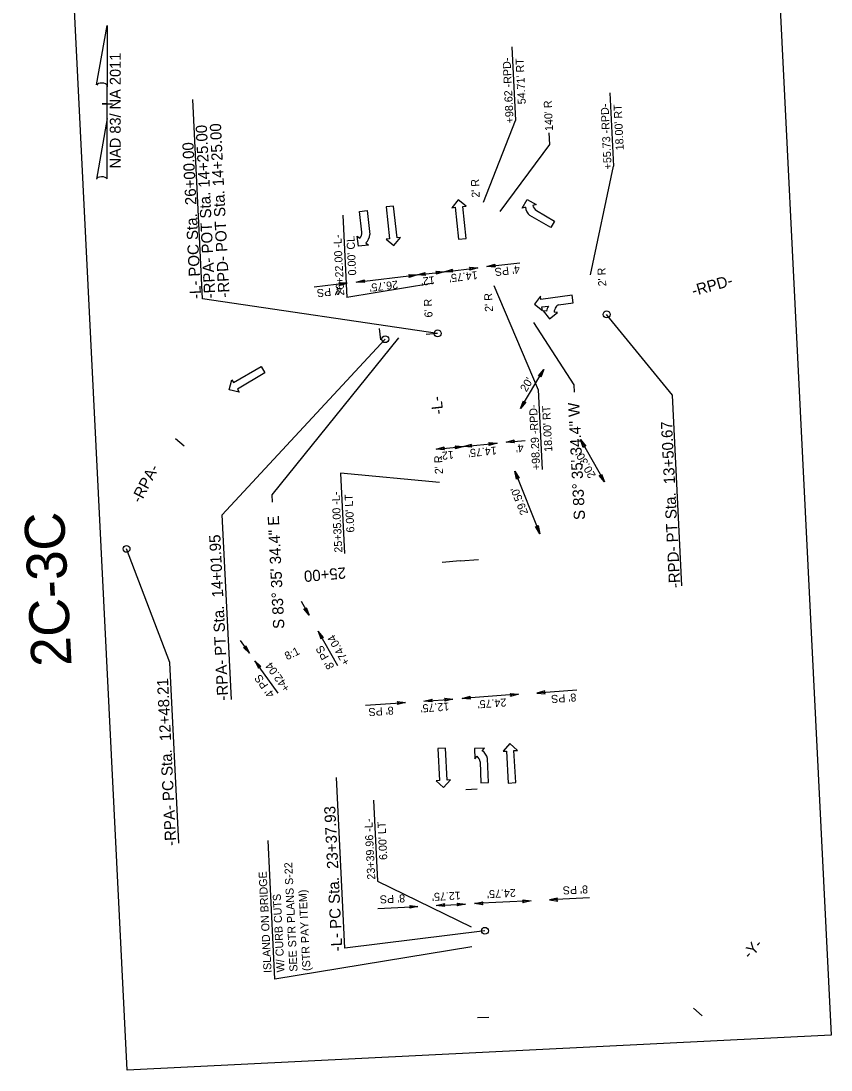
# Model space of a CAD drawing. Extents: x 1807485 to 1808169, y 913841 to 915733.
# Drawn here: x 1807681.6 to 1808035.7, y 914781.9 to 915240.5 of the extents above; entities that cross this region are included whole.
import ezdxf

# ---------------------------------------------------------------- set-up
doc = ezdxf.new("R2010")
doc.units = 0
for name, color, linetype in [('Prop Dimension', 7, 'Continuous'), ('Prop Horizontal Alignment Direction Label', 7, 'Continuous'), ('Prop Horizontal Alignment Station Label', 7, 'Continuous'), ('Prop Horizontal Alignment Tick Label', 7, 'Continuous'), ('Prop Horizontal Alignment Tick Large', 7, 'Continuous'), ('Prop Horizontal Alignment Tick Small', 7, 'Continuous'), ('Prop Lane Arrow CELL', 7, 'Continuous'), ('Prop North Arrow NAD83 for Plan Sheets CELL', 7, 'Continuous'), ('Scratch_Level_3', 7, 'Continuous'), ('Scratch_Level_6', 7, 'Continuous')]:
    doc.layers.add(name, color=color, linetype=linetype)

msp = doc.modelspace()

# ---------------------------------------------------------------- linework, layer by layer
at = {"layer": 'Prop Dimension'}
for p, q in [((1807896.2, 915229.15), (1807897.79, 915197.06)), ((1807939.04, 915209.15), (1807940.63, 915177.06)), ((1807883.84, 915161.26), (1807897.79, 915197.06)), ((1807912.37, 915191.57), (1807912.62, 915186.54)), ((1807912.62, 915186.54), (1807890.86, 915157.25)), ((1807930.56, 915129.57), (1807940.63, 915177.06)), ((1807822.31, 915155.59), (1807824.1, 915119.62)), ((1807861.19, 915125.8), (1807824.1, 915119.62)), ((1807888.27, 915124.82), (1807907.72, 915079.22)), ((1807907.72, 915079.22), (1807909.45, 915044.42)), ((1807864.5, 915038.74), (1807821.27, 915042.81)), ((1807821.27, 915042.81), (1807823.02, 915007.66)), ((1807835.63, 914899.92), (1807837.38, 914864.5)), ((1807792.62, 914821.54), (1807789.61, 914882.28)), ((1807837.38, 914864.5), (1807878.34, 914844.4)), ((1807878.75, 914835.67), (1807792.62, 914821.54))]:
    msp.add_line(p, q, dxfattribs=at)
at = {"layer": 'Prop Horizontal Alignment Direction Label'}
for p, q in [((1807923.42, 915081.37), (1807905.83, 915108.68)), ((1807791.35, 915033.3), (1807846.77, 915102.05)), ((1807923.58, 915078.19), (1807923.42, 915081.37)), ((1807791.5, 915030.13), (1807791.35, 915033.3))]:
    msp.add_line(p, q, dxfattribs=at)
at = {"layer": 'Prop Horizontal Alignment Station Label'}
for p, q in [((1807760.98, 915119.1), (1807756.66, 915206.16)), ((1807863.73, 915103.95), (1807760.98, 915119.1)), ((1807966.37, 915076.91), (1807937.6, 915112.25)), ((1807840.83, 915101.38), (1807769.55, 915024.57)), ((1807970.51, 914993.57), (1807966.37, 915076.91)), ((1807773.56, 914943.92), (1807769.55, 915024.57)), ((1807746.7, 914960.03), (1807727.75, 915009.71)), ((1807750.63, 914881), (1807746.7, 914960.03)), ((1807823.18, 914835.12), (1807819.47, 914909.79)), ((1807884.43, 914842.75), (1807823.18, 914835.12))]:
    msp.add_line(p, q, dxfattribs=at)
for centre in [(1807937.6, 915112.25), (1807863.73, 915103.95), (1807840.83, 915101.38), (1807727.75, 915009.71), (1807884.43, 914842.75)]:
    msp.add_circle(centre, 1.5, dxfattribs=at)
at = {"layer": 'Prop Horizontal Alignment Tick Large'}
for q in [(1807865.68, 915003.75), (1807881.62, 915005.14)]:
    msp.add_line((1807873.65, 915004.45), q, dxfattribs=at)
at = {"layer": 'Prop Horizontal Alignment Tick Small'}
for p, q in [((1807838.89, 915101.15), (1807838.26, 915106.11)), ((1807863.73, 915103.95), (1807858.76, 915103.39)), ((1807752.97, 915054.58), (1807749.15, 915057.82)), ((1807881.07, 914904.73), (1807876.08, 914904.42)), ((1807979.31, 914805.51), (1807975.62, 914808.87)), ((1807886.18, 914804.86), (1807881.19, 914804.63))]:
    msp.add_line(p, q, dxfattribs=at)
at = {"layer": 'Prop Lane Arrow CELL'}
for p, q in [((1807872.77, 915162.36), (1807869.92, 915158.89)), ((1807876.19, 915159.56), (1807872.77, 915162.36)), ((1807900.7, 915158.7), (1807902.88, 915162.53)), ((1807902.88, 915162.53), (1807906.79, 915160.3)), ((1807906.79, 915160.3), (1807905.35, 915159.92)), ((1807829.63, 915157.28), (1807832.91, 915157.64)), ((1807830.62, 915148.18), (1807829.63, 915157.28)), ((1807832.91, 915157.64), (1807834.05, 915147.15)), ((1807844.48, 915159.59), (1807841.2, 915159.23)), ((1807841.2, 915159.23), (1807842.7, 915145.31)), ((1807845.98, 915145.67), (1807844.48, 915159.59)), ((1807869.92, 915158.89), (1807871.41, 915159.05)), ((1807871.41, 915159.05), (1807872.92, 915145.13)), ((1807874.7, 915159.4), (1807876.19, 915159.56)), ((1807876.2, 915145.48), (1807874.7, 915159.4)), ((1807902.13, 915159.08), (1807900.7, 915158.7)), ((1807913.16, 915150.2), (1807904.05, 915155.52)), ((1807906.93, 915157.67), (1807914.82, 915153.05)), ((1807914.82, 915153.05), (1807913.16, 915150.2)), ((1807829.13, 915142.04), (1807828.59, 915146.51)), ((1807828.59, 915146.51), (1807829.75, 915145.58)), ((1807833.5, 915142.56), (1807829.13, 915142.04)), ((1807832.34, 915143.49), (1807833.5, 915142.56)), ((1807842.7, 915145.31), (1807841.21, 915145.15)), ((1807841.21, 915145.15), (1807844.63, 915142.35)), ((1807844.63, 915142.35), (1807847.47, 915145.83)), ((1807847.47, 915145.83), (1807845.98, 915145.67)), ((1807872.92, 915145.13), (1807876.2, 915145.48)), ((1807908.69, 915120.24), (1807906.05, 915116.7)), ((1807908.89, 915118.75), (1807908.69, 915120.24)), ((1807922.56, 915120.63), (1807908.89, 915118.75)), ((1807923.01, 915117.36), (1807922.56, 915120.63)), ((1807906.05, 915116.7), (1807909.55, 915114)), ((1807909.34, 915115.48), (1807912.17, 915115.87)), ((1807909.55, 915114), (1807909.34, 915115.48)), ((1807909.87, 915113.84), (1807912.57, 915110.33)), ((1807911.36, 915113.64), (1807909.87, 915113.84)), ((1807916.62, 915116.48), (1807923.01, 915117.36)), ((1807912.57, 915110.33), (1807916.09, 915113.03)), ((1807916.09, 915113.03), (1807914.65, 915113.23)), ((1807774.51, 915082.39), (1807786.58, 915089.48)), ((1807788.25, 915086.63), (1807776.18, 915079.54)), ((1807786.58, 915089.48), (1807788.25, 915086.63)), ((1807772.66, 915079.32), (1807773.75, 915083.68)), ((1807773.75, 915083.68), (1807774.51, 915082.39)), ((1807776.94, 915078.25), (1807772.66, 915079.32)), ((1807776.18, 915079.54), (1807776.94, 915078.25)), ((1807867.13, 914922.59), (1807863.84, 914922.42)), ((1807863.84, 914922.42), (1807864.58, 914908.44)), ((1807867.88, 914908.61), (1807867.13, 914922.59)), ((1807884.25, 914922.56), (1807879.85, 914922.43)), ((1807879.85, 914922.43), (1807879.99, 914917.93)), ((1807883.24, 914921.47), (1807884.25, 914922.56)), ((1807895.33, 914924.57), (1807892.31, 914921.25)), ((1807892.31, 914921.25), (1807893.8, 914921.33)), ((1807893.8, 914921.33), (1807894.55, 914907.35)), ((1807898.6, 914921.58), (1807895.33, 914924.57)), ((1807897.1, 914921.5), (1807898.6, 914921.58)), ((1807897.84, 914907.52), (1807897.1, 914921.5)), ((1807879.99, 914917.93), (1807880.99, 914919.02)), ((1807882.25, 914916.57), (1807882.63, 914907.43)), ((1807885.92, 914907.57), (1807885.48, 914918.11)), ((1807864.58, 914908.44), (1807863.08, 914908.36)), ((1807863.08, 914908.36), (1807866.35, 914905.38)), ((1807866.35, 914905.38), (1807869.38, 914908.69)), ((1807869.38, 914908.69), (1807867.88, 914908.61)), ((1807882.63, 914907.43), (1807885.92, 914907.57)), ((1807894.55, 914907.35), (1807897.84, 914907.52))]:
    msp.add_line(p, q, dxfattribs=at)
for centre, radius, start, end in [((1807908.56, 915160.48), 3.27, 190.0189, 239.6771), ((1807907.35, 915159.59), 5.25, 185.6893, 231.001), ((1807827.38, 915147.82), 3.27, 316.5434, 6.2016), ((1807828.82, 915147.38), 5.25, 312.2138, 357.5255), ((1807915.8, 915113.35), 4.43, 145.3596, 176.2382), ((1807919.07, 915112.93), 4.43, 145.2658, 176.1194), ((1807917.59, 915114.15), 2.52, 112.4439, 148.7559), ((1807880.35, 914917.1), 5.25, 11.0556, 56.3673), ((1807878.99, 914916.45), 3.27, 2.3796, 52.0377)]:
    msp.add_arc(centre, radius, start, end, dxfattribs=at)
at = {"layer": 'Prop North Arrow NAD83 for Plan Sheets CELL'}
for p, q in [((1807714.68, 915212.54), (1807719.28, 915238.49)), ((1807719.3, 915238.49), (1807719.28, 915238.49)), ((1807719.3, 915238.49), (1807719.28, 915238.49)), ((1807719.3, 915238.49), (1807719.3, 915211.72)), ((1807719.3, 915197.84), (1807719.3, 915212.51)), ((1807719.3, 915211.72), (1807719.3, 915212.48)), ((1807717.06, 915204.33), (1807717.04, 915204.33)), ((1807719.05, 915204.33), (1807717.06, 915204.33)), ((1807717.09, 915204.33), (1807721.57, 915204.33)), ((1807719.3, 915197.84), (1807714.63, 915171.38)), ((1807719.33, 915171.49), (1807719.3, 915197.84))]:
    msp.add_line(p, q, dxfattribs=at)
for centre, start_param, end_param in [((1807717, 915212.26), 0.216388, 2.908219), ((1807717, 915171.28), 0.201328, 3.141593)]:
    msp.add_ellipse(centre, major_axis=(2.37, -0.02), ratio=0.461098, start_param=start_param, end_param=end_param, dxfattribs=at)
at = {"layer": 'Scratch_Level_3'}
msp.add_lwpolyline([(1807728.07, 914781.87), (1807681.6, 915717.81), (1807989.22, 915733.08), (1808035.69, 914797.14)], close=True, dxfattribs=at)
at = {"layer": 'Scratch_Level_6'}
for p, q in [((1807866.65, 915130.91), (1807881.3, 915132.65)), ((1807885.27, 915133.12), (1807899.69, 915134.84)), ((1807828.18, 915126.33), (1807854.74, 915129.49)), ((1807854.74, 915129.49), (1807866.65, 915130.91)), ((1807824.2, 915125.86), (1807809.79, 915124.14)), ((1807899.91, 915071.03), (1807910.16, 915088.21)), ((1807863.07, 915053.29), (1807875.01, 915054.47)), ((1807875.01, 915054.47), (1807889.68, 915055.94)), ((1807893.66, 915056.33), (1807902.01, 915057.16)), ((1807926.17, 915057.52), (1807936.66, 915038.98)), ((1807897.47, 915043.74), (1807908.41, 915016.34)), ((1807807.57, 914980.72), (1807804.2, 914986.67)), ((1807820.13, 914958.56), (1807811.49, 914973.81)), ((1807781.52, 914964.07), (1807777.53, 914969.62)), ((1807794.06, 914946.58), (1807783.85, 914960.82)), ((1807857.71, 914943.15), (1807870.42, 914944.06)), ((1807899.1, 914946.13), (1807874.41, 914944.35)), ((1807924.56, 914947.96), (1807907.08, 914946.7)), ((1807832.25, 914941.32), (1807849.73, 914942.57)), ((1807930.07, 914857.09), (1807912.57, 914856.22)), ((1807837.63, 914852.52), (1807855.14, 914853.39)), ((1807863.13, 914853.78), (1807875.86, 914854.41)), ((1807904.58, 914855.83), (1807879.86, 914854.61))]:
    msp.add_line(p, q, dxfattribs=at)
for points in [[(1807877.65, 915132.84), (1807881.3, 915132.65), (1807877.78, 915131.59), (1807878.16, 915132.28)], [(1807888.92, 915132.93), (1807885.27, 915133.12), (1807888.79, 915134.19), (1807888.41, 915133.5)], [(1807851.09, 915129.68), (1807854.74, 915129.49), (1807851.22, 915128.43), (1807851.6, 915129.12)], [(1807858.39, 915129.3), (1807854.74, 915129.49), (1807858.26, 915130.55), (1807857.88, 915129.86)], [(1807863.01, 915131.1), (1807866.65, 915130.91), (1807863.14, 915129.85), (1807863.52, 915130.54)], [(1807870.3, 915130.72), (1807866.65, 915130.91), (1807870.17, 915131.97), (1807869.79, 915131.28)], [(1807820.7, 915124.82), (1807824.2, 915125.86), (1807820.53, 915126.07), (1807821.07, 915125.48)], [(1807831.82, 915126.14), (1807828.18, 915126.33), (1807831.7, 915127.39), (1807831.31, 915126.7)], [(1807907.78, 915085.43), (1807910.16, 915088.21), (1807908.85, 915084.77), (1807908.54, 915085.49)], [(1807902.29, 915073.8), (1807899.91, 915071.03), (1807901.22, 915074.46), (1807901.53, 915073.74)], [(1807866.71, 915053.03), (1807863.07, 915053.29), (1807866.6, 915054.28), (1807866.21, 915053.6)], [(1807871.36, 915054.74), (1807875.01, 915054.47), (1807871.47, 915053.48), (1807871.86, 915054.16)], [(1807878.65, 915054.21), (1807875.01, 915054.47), (1807878.54, 915055.47), (1807878.15, 915054.79)], [(1807886.04, 915056.2), (1807889.68, 915055.94), (1807886.14, 915054.94), (1807886.54, 915055.62)], [(1807897.31, 915056.07), (1807893.66, 915056.33), (1807897.2, 915057.33), (1807896.81, 915056.65)], [(1807927.4, 915054.08), (1807926.17, 915057.52), (1807928.51, 915054.68), (1807927.73, 915054.77)], [(1807898.23, 915040.17), (1807897.47, 915043.74), (1807899.41, 915040.61), (1807898.64, 915040.8)], [(1807935.43, 915042.42), (1807936.66, 915038.98), (1807934.32, 915041.81), (1807935.11, 915041.73)], [(1807907.65, 915019.92), (1807908.41, 915016.34), (1807906.48, 915019.47), (1807907.24, 915019.28)], [(1807806.33, 914984.16), (1807807.57, 914980.72), (1807805.23, 914983.56), (1807806.01, 914983.47)], [(1807813.8, 914970.98), (1807811.49, 914973.81), (1807812.72, 914970.34), (1807813.05, 914971.06)], [(1807779.92, 914967.35), (1807781.52, 914964.07), (1807778.89, 914966.64), (1807779.68, 914966.63)], [(1807786.45, 914958.25), (1807783.85, 914960.82), (1807785.44, 914957.5), (1807785.69, 914958.25)], [(1807866.79, 914944.42), (1807870.42, 914944.06), (1807866.86, 914943.16), (1807867.27, 914943.84)], [(1807878.05, 914943.99), (1807874.41, 914944.35), (1807877.98, 914945.25), (1807877.56, 914944.58)], [(1807895.46, 914946.49), (1807899.1, 914946.13), (1807895.53, 914945.23), (1807895.95, 914945.9)], [(1807910.62, 914947.58), (1807907.08, 914946.7), (1807910.73, 914946.32), (1807910.23, 914946.93)], [(1807846.09, 914942.93), (1807849.73, 914942.57), (1807846.16, 914941.68), (1807846.57, 914942.35)], [(1807861.34, 914942.79), (1807857.71, 914943.15), (1807861.27, 914944.05), (1807860.86, 914943.37)], [(1807916.13, 914857.02), (1807912.57, 914856.22), (1807916.21, 914855.76), (1807915.72, 914856.38)], [(1807851.51, 914853.83), (1807855.14, 914853.39), (1807851.55, 914852.57), (1807851.98, 914853.23)], [(1807866.75, 914853.34), (1807863.13, 914853.78), (1807866.71, 914854.6), (1807866.28, 914853.94)], [(1807872.23, 914854.85), (1807875.86, 914854.41), (1807872.28, 914853.59), (1807872.7, 914854.25)], [(1807883.48, 914854.16), (1807879.86, 914854.61), (1807883.44, 914855.42), (1807883.01, 914854.76)], [(1807900.95, 914856.27), (1807904.58, 914855.83), (1807900.99, 914855.01), (1807901.42, 914855.67)]]:
    msp.add_lwpolyline(points, close=True, dxfattribs=at)

# ---------------------------------------------------------------- texts
at = {"layer": 'Prop Dimension'}
for s, p in [('+98.62 -RPD-', (1807896.99, 915195.86)), ("54.71' RT", (1807902.27, 915204.19)), ("140' R", (1807914.21, 915192.5)), ('+55.73 -RPD-', (1807939.83, 915175.73)), ("18.00' RT", (1807945.11, 915184.05)), ("2' R", (1807882.16, 915163.35)), ('26+22.00 -L-', (1807822.93, 915120.56)), ("0.00' CL", (1807828.18, 915129.35)), ("2' R", (1807937.46, 915124.6)), ("6' R", (1807861.55, 915110.97)), ("2' R", (1807887.93, 915113.48)), ('+98.29 -RPD-', (1807908.59, 915044.24)), ("18.00' RT", (1807913.89, 915052.26)), ("2' R", (1807866.08, 915042.5)), ('25+35.00 -L-', (1807822.13, 915008.16)), ("6.00' LT", (1807827.38, 915016.95)), ('23+39.96 -L-', (1807836.49, 914865.2)), ("6.00' LT", (1807841.75, 914873.8)), ('SEE STR PLANS S-22', (1807802.51, 914824.95)), ('ISLAND ON BRIDGE', (1807791.15, 914824.39)), ('W/ CURB CUTS', (1807796.83, 914824.67)), ('(STR PAY ITEM)', (1807808.19, 914825.24))]:
    msp.add_text(s, height=3.5, rotation=92.8422, dxfattribs=at).set_placement(p)
at = {"layer": 'Prop Horizontal Alignment Direction Label'}
for s, rotation, p in [('-RPD-', 15.5231, (1807975.54, 915120.12)), ('-L-', 96.3677, (1807866.28, 915068.72)), ('S 83%%d 35\' 34.4" W', 92.8422, (1807928.2, 915022.48)), ('-RPA-', 62.2864, (1807733.83, 915029.35)), ('S 83%%d 35\' 34.4" E', 92.8422, (1807796.76, 914974.86)), ('-Y-', 47.6532, (1808000.26, 914830.09))]:
    msp.add_text(s, height=4.9, rotation=rotation, dxfattribs=at).set_placement(p)
at = {"layer": 'Prop Horizontal Alignment Station Label'}
for s, p in [('-RPA- POT Sta. 14+25.00', (1807766.58, 915119.37)), ('-RPD- POT Sta. 14+25.00', (1807772.78, 915119.68)), ('-L- POC Sta.  26+00.00', (1807760.38, 915119.06)), ('-RPD- PT Sta.  13+50.67', (1807969.8, 914992.68)), ('-RPA- PT Sta.  14+01.95', (1807772.3, 914943.51)), ('-RPA- PC Sta.  12+48.21', (1807749.52, 914879.98)), ('-L- PC Sta.  23+37.93', (1807822.12, 914833.91))]:
    msp.add_text(s, height=4.9, rotation=92.8422, dxfattribs=at).set_placement(p)
at = {"layer": 'Prop Horizontal Alignment Tick Label'}
msp.add_text('25+00', height=4.9, rotation=184.9747, dxfattribs=at).set_placement((1807823.43, 915001.68))
at = {"layer": 'Prop North Arrow NAD83 for Plan Sheets CELL'}
msp.add_text('NAD 83/ NA 2011', height=4.76, rotation=90, dxfattribs=at).set_placement((1807725.19, 915176.05))
at = {"layer": 'Scratch_Level_3'}
msp.add_text('2C-3C', height=17.5, rotation=92.8422, dxfattribs=at).set_placement((1807703.75, 914958.7))
at = {"layer": 'Scratch_Level_6'}
for s, rotation, p in [("4' PS", 186.7856, (1807899.48, 915133.72)), ("12'", 186.7856, (1807862.31, 915128.97)), ("14.75'", 186.7856, (1807881.02, 915131.2)), ("4' PS", 186.7856, (1807821.72, 915124.47)), ("26.75'", 186.7856, (1807846.22, 915127.05)), ("20'", 59.1968, (1807902.53, 915078.07)), ("14.75'", 185.6859, (1807889.38, 915054.49)), ("4'", 185.6859, (1807901.15, 915055.66)), ("12'", 185.6859, (1807870.63, 915052.62)), ("20.30'", 119.5113, (1807932.99, 915041.83)), ("29.50'", 111.7763, (1807903.4, 915025.36)), ('+74.04', 119.5395, (1807825.57, 914959.96)), ("8' PS", 119.5395, (1807818.72, 914958.24)), ('8:1', 25.9838, (1807797.91, 914961)), ('+42.04', 125.6513, (1807799.42, 914948.81)), ("4' PS", 125.6513, (1807792.64, 914946.2)), ("24.75'", 184.1153, (1807893.64, 914944.35)), ("8' PS", 184.1153, (1807924.24, 914946.55)), ("8' PS", 184.1153, (1807844.39, 914940.81)), ("12.75'", 184.1153, (1807868.69, 914942.56)), ("8' PS", 182.8261, (1807929.38, 914862.63)), ("8' PS", 182.8261, (1807849.42, 914858.69)), ("12.75'", 182.8261, (1807873.75, 914859.89)), ("24.75'", 182.8261, (1807897.82, 914861.08))]:
    msp.add_text(s, height=3.5, rotation=rotation, dxfattribs=at).set_placement(p)

doc.saveas('drawing.dxf')
